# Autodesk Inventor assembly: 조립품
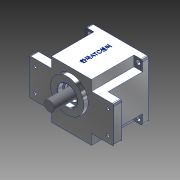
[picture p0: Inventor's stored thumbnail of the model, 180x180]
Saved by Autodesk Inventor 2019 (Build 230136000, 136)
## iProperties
Created: 2020-01
Part Number: 조립품
Material: 일반
Document SubType Name: Assembly
Designer: 323-8
Author: 323-8
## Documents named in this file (9)
- C:\Users\323-8\Desktop\700119V1001\조립품.iam
- C:\Users\323-8\Desktop\700119V1001\본체.ipt
- C:\Users\323-8\Desktop\700119V1001\커버.ipt
- C:\Users\323-8\Desktop\700119V1001\메인 축.ipt
- C:\Users\323-8\Desktop\700119V1001\베어링 608.ipt
- C:\Users\323-8\Desktop\700119V1001\오일 실 8 22 7.ipt
- C:\Users\323-8\Desktop\700119V1001\서브 축.ipt
- C:\Users\323-8\Desktop\700119V1001\베어링 6003.ipt
- C:\Users\323-8\Desktop\700119V1001\볼트 M4.ipt
